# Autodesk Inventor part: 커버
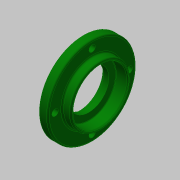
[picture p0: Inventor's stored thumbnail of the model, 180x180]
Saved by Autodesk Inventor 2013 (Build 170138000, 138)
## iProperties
Created: 2018-11
Part Number: 커버
Material: 알루미늄 6061
Document SubType Name: Modeling
Designer: mduedu
Density: 1 g/cm^3
d0: 62.000 mm
d2: 42.000 mm
d3: 40.000 mm
d4: 3.000 mm
d5: 6.000 mm
d6: 15.000 mm
d8: 38.000 mm
d10: 28.000 mm
d11: 33.000 mm
d12: 3.000 mm
d13: 8.300 mm
d15: 0.300 mm
d16: 0.800 mm
d18: 30.00 deg
d19: 1.000 mm
d20: 0.500 mm
d23: 52.000 mm
d24: 4.000 ul
d28: 4.500 mm
d26: 360.00 deg
Author: mduedu
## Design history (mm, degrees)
sketch "스케치1"
  geometry: L1 (0, 0)-(3, 0); L2 (3, 0)-(3, 20); L3 (3, 20)-(0, 20); L4 (0, 20)-(0, 0); L5 (3, 0)-(9, 0); L6 (9, 0)-(9, 31); L7 (9, 31)-(3, 31); L8 (3, 31)-(3, 0); L9 (9, 0)-(15, 0); L10 (15, 0)-(15, 21); L11 (15, 21)-(9, 21); L12 (9, 21)-(9, 0)
  constraints: 24 end point, 6 parallel, 3 horizontal, 3 perpendicular
  dimensions: "d0" = 62 diameter of L7 L5; "d2" = 42 diameter of L11 L9; "d3" = 40 diameter of L3 L1; "d4" = 3 distance of L2.end L3.end; "d5" = 6 distance of L6.end L7.end; "d6" = 15 distance between parallel lines of L10 L4
revolve "회전1" sketch "스케치1" stored, may be unused: angle "d7" = 90 deg
sketch "스케치2"
  geometry: L1 (0, -20)-(0, 20) reference; L2 (0, 20)-(3, 20) reference; L3 (3, 20)-(3, 31) reference; L4 (3, 31)-(9, 31) reference; L5 (9, 31)-(9, 21) reference; L6 (9, 21)-(15, 21) reference; L7 (15, 21)-(15, -21) reference; L8 (15, -21)-(9, -21) reference; L9 (9, -21)-(9, -31) reference; L10 (9, -31)-(3, -31) reference; L11 (3, -31)-(3, -20) reference; L12 (3, -20)-(0, -20) reference; L13 (0, 0)-(3, 0); L14 (3, 0)-(3, 16.5); L15 (3, 16.5)-(0, 16.5); L16 (0, 16.5)-(0, 0); L17 (3, 0)-(6.7, 0); L18 (6.7, 0)-(6.7, 14); L19 (6.7, 14)-(3, 14); L20 (3, 14)-(3, 0); L21 (6.7, 0)-(15, 0); L22 (15, 0)-(15, 19); L23 (15, 19)-(6.7, 19); L24 (6.7, 19)-(6.7, 0)
  constraints: 24 end point, 6 parallel, 3 horizontal, 3 perpendicular, 1 point on line
  dimensions: "d8" = 38 diameter of L23 L21; "d10" = 28 diameter of L19 L17; "d11" = 33 diameter of L15 L13; "d12" = 3 distance of L14.end L15.end; "d13" = 8.3 distance of L22.end L23.end
revolve "회전2" sketch "스케치2" stored, may be unused: angle "d14" = 90 deg
fillet "모깎기1" dims "d15" = 0.3
chamfer "모따기1" distance "d16" = 0.8; stored, may be unused: second distance "d17" = 2, angle "d18" = 30 deg
fillet "모깎기2" dims "d19" = 1
chamfer "모따기2" distance "d20" = 0.5; stored, may be unused: second distance "d21" = 2, angle "d22" = 30 deg
sketch "스케치3" dims "d23" = 52
  geometry: 6 further points
  constraints: 2 vertical alignment, 1 coincident, 7 other
  dimensions: "d26" = 360 deg dimension on point (0, 0) point (0, 26) (derived)
sketch "스케치4"
  geometry: 4 further points
  constraints: 4 other
hole "구멍1" sketch "스케치4" at (-26, 0), (0, -26), (26, 0), (0, 26) diameter "d28" = 4.5; stored, may be unused: countersink angle "d32" = 90 deg, drill point angle "d34" = 0 deg; dims "d29" = 6, "d30" = 8, "d31" = 4.6, "d33" = 8
node "솔리드1"
node "절단 모서리 투영1"
other parameters: "d24" = 4
